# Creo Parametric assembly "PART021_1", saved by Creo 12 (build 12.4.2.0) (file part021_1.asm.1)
Units: Custom; MM, KILOGRAM, SECS

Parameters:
  PTC_WM_ITERATION = "0"
  PTC_WM_VERSION = "-.0"
  PTC_WM_LIFECYCLE_STATE = "In Work"
  PTC_WM_LIFECYCLE = "MO_CADDocument"
  PTC_WM_CREATED_BY = "Maximilian Roepper (Z0017RMS: MO)"
  PTC_WM_CREATED_ON = "18-Sep-26 11:36:42 AM"
  PTC_WM_MODIFIED_BY = "Maximilian Roepper (Z0017RMS: MO)"
  PTC_WM_MODIFIED_ON = "18-Sep-26 11:36:46 AM"
  PDMLINKNUMBER = "PDM000071455087"
  PTC_WM_NUMBER = "PDM000071455087"

Other parameters: WEIGHT, WEIGHT_FACTOR, WEIGHT_ADD, MC_ERRORS, SUPPLIER

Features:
  1. coordinate system
  2. imported feature
  3. component "SHAPESTRING271_1"

Other named items: DRW_VIEW_ORG, ROUGH-GROB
